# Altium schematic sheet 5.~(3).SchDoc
size 609 x 444 mm
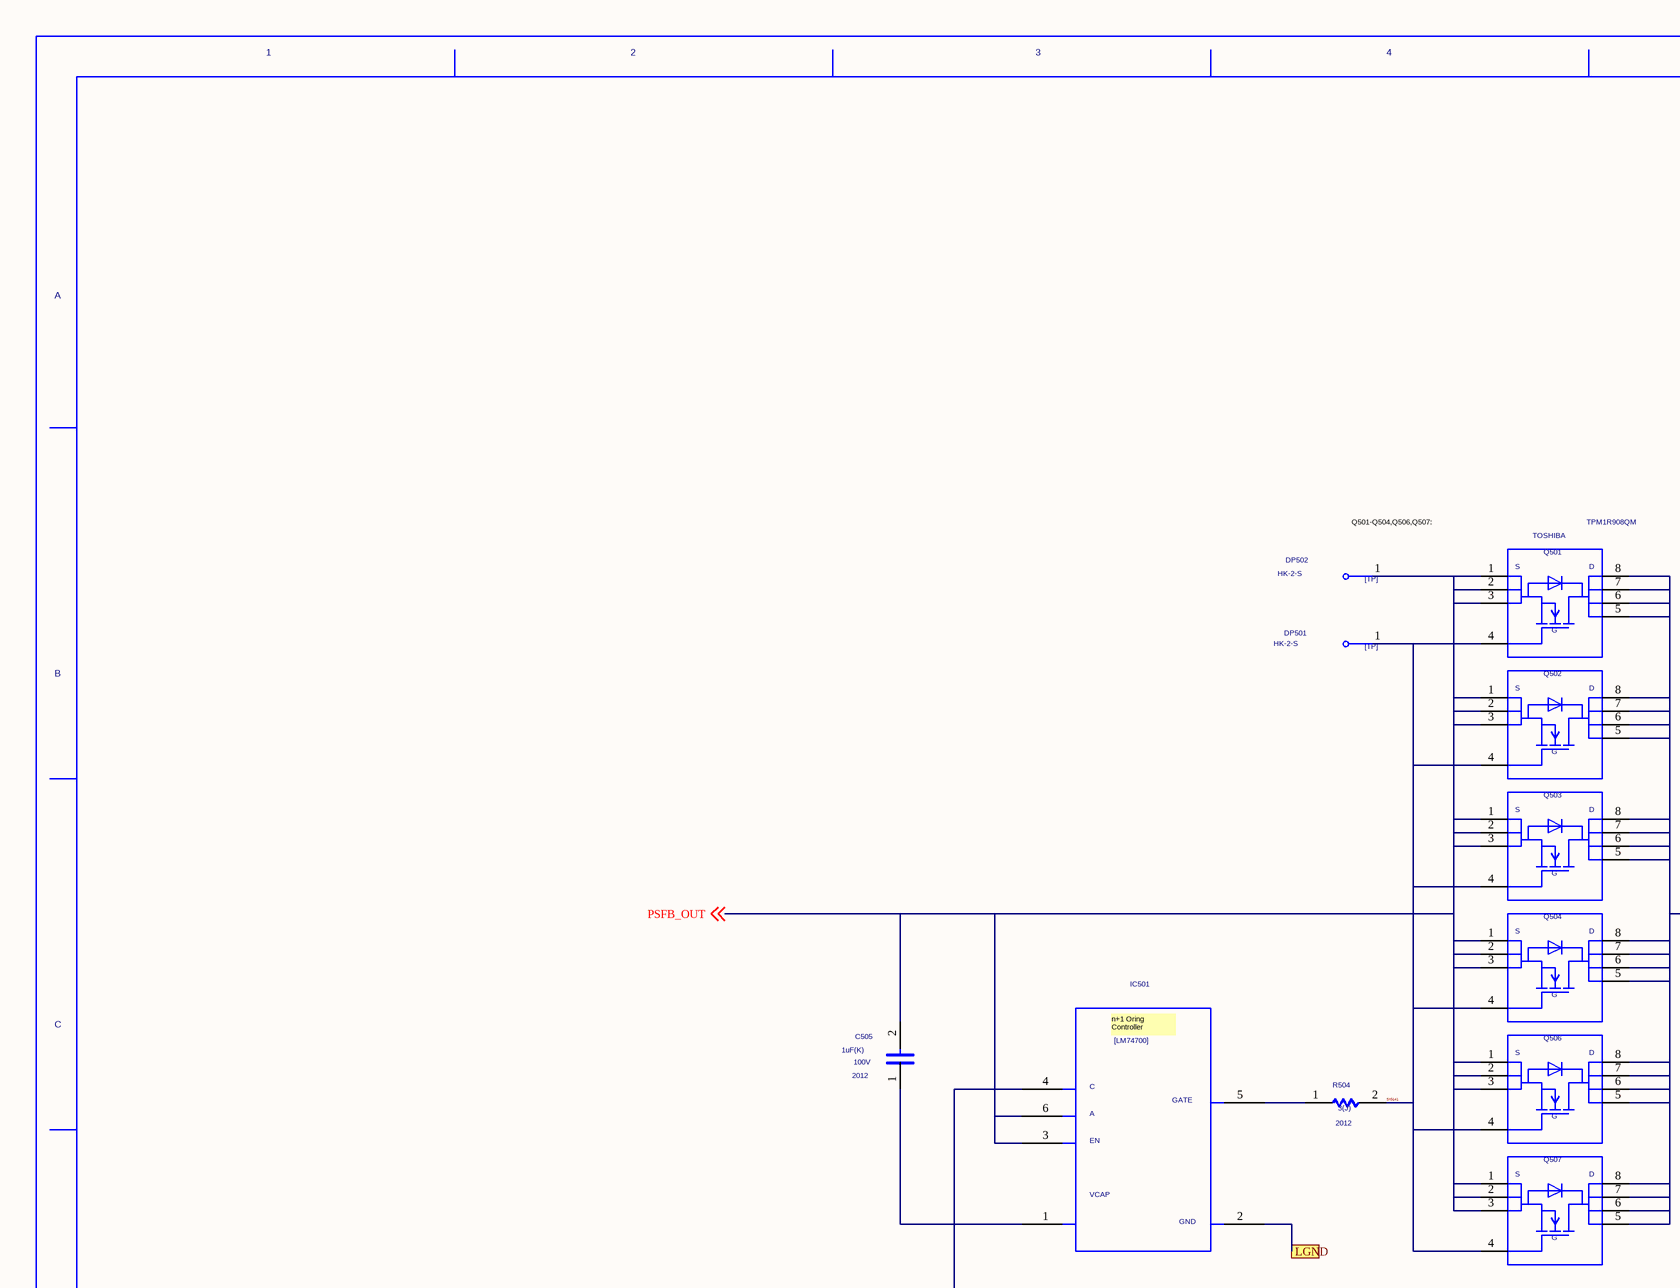
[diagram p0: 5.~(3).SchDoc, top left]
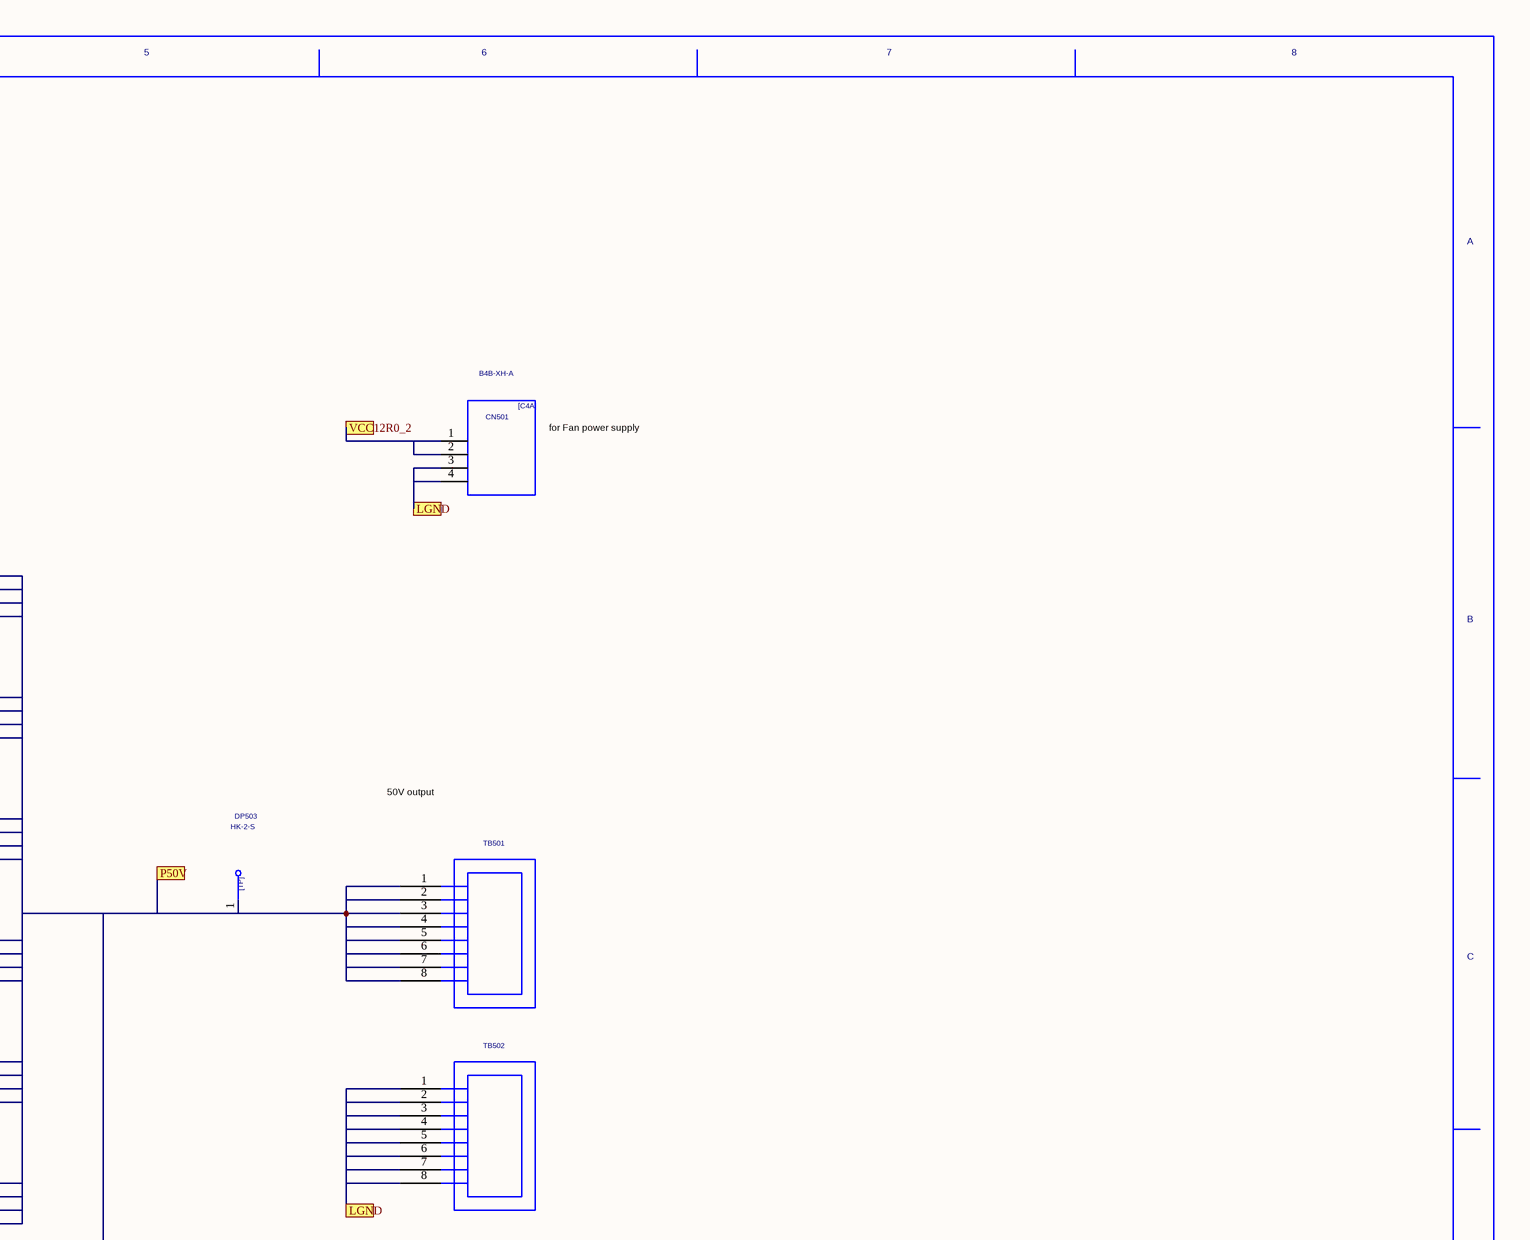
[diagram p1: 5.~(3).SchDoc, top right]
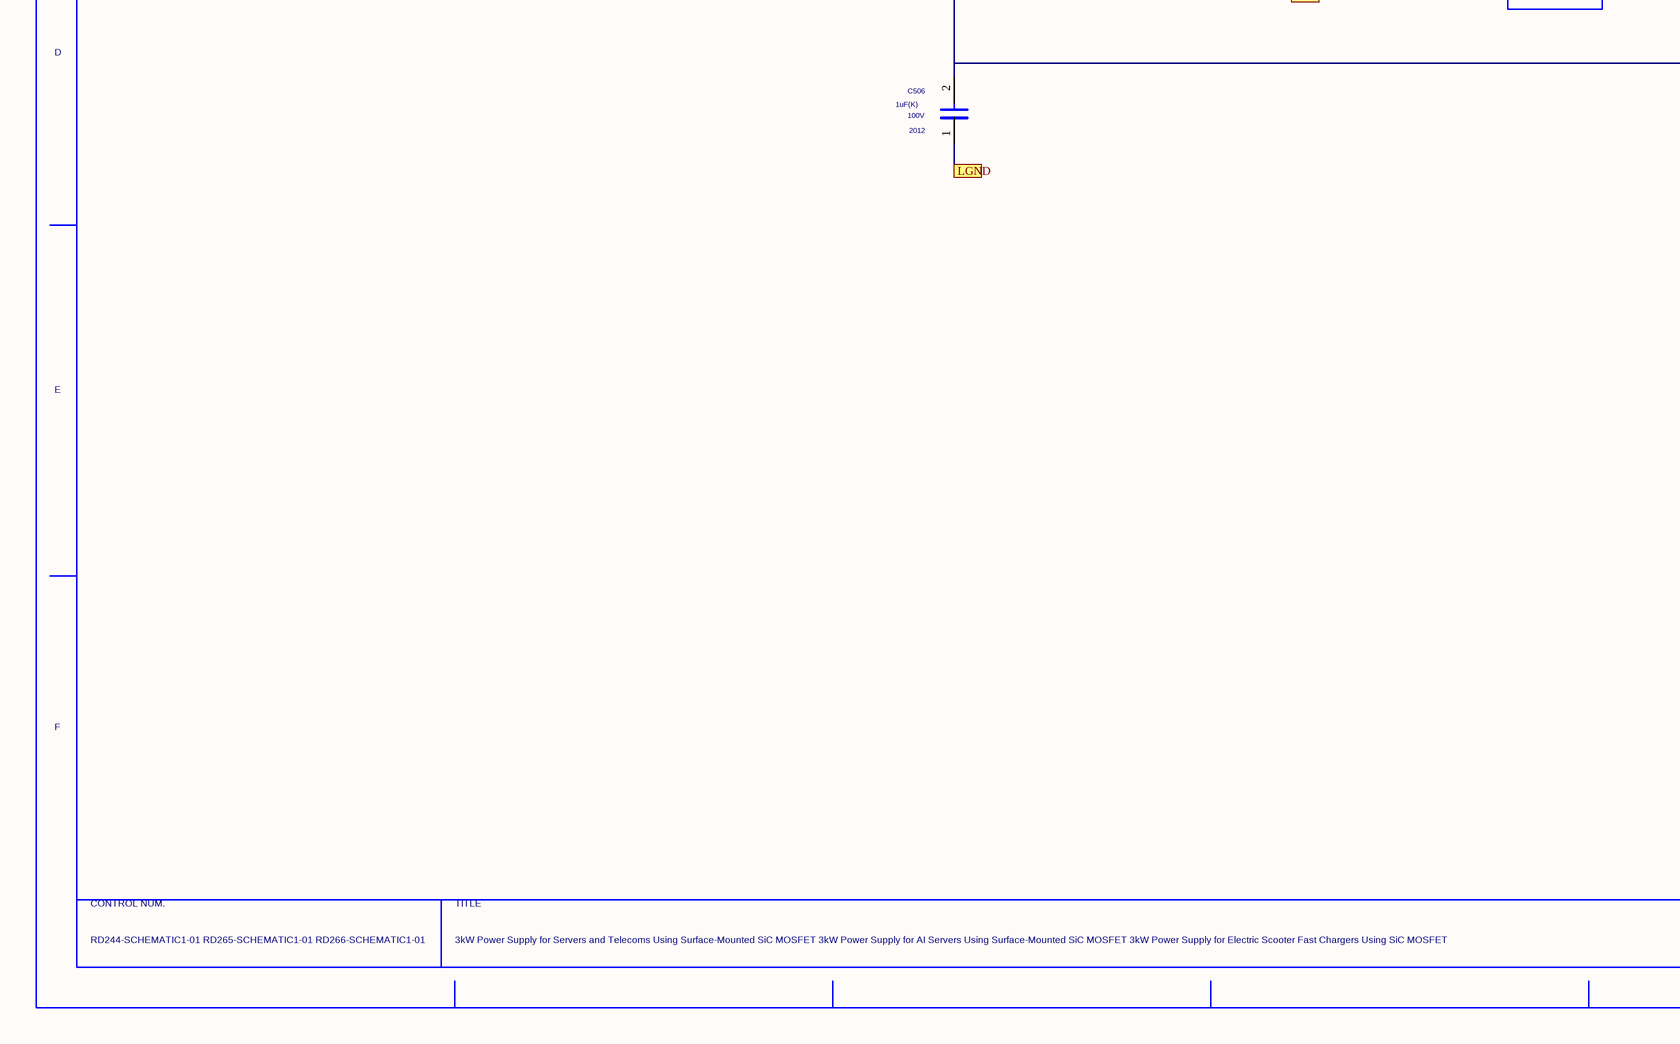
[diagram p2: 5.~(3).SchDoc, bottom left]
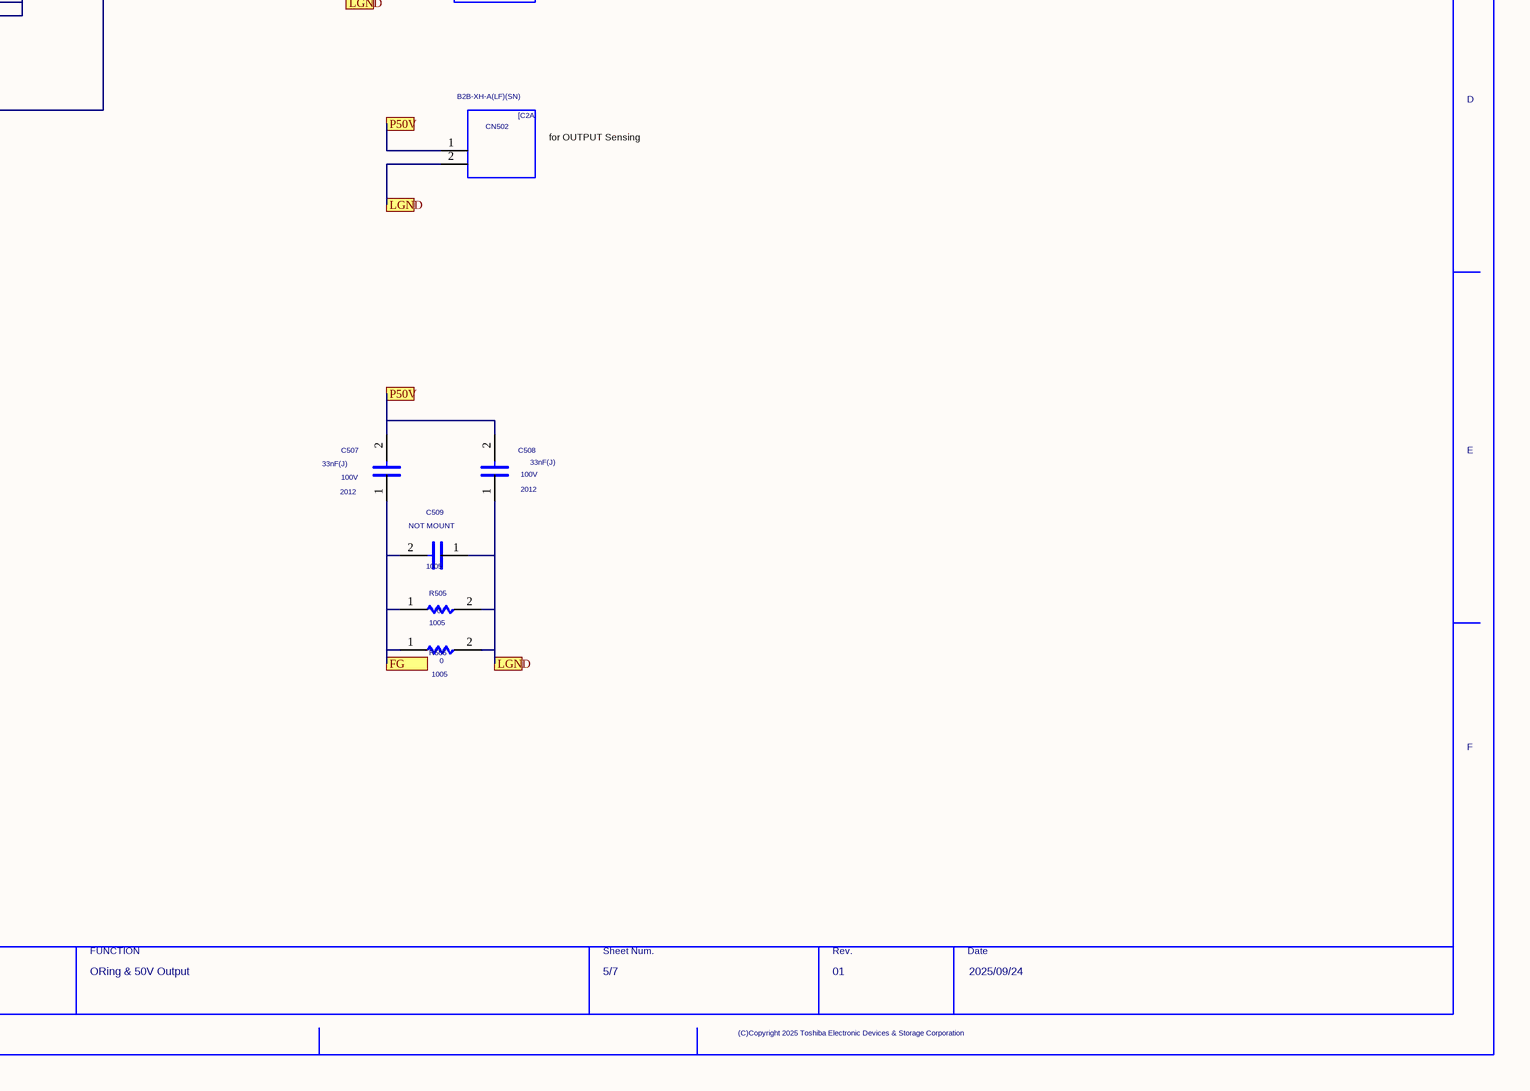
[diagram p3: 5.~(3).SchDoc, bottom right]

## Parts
C505  VAL1: 1uF(K)  VAL2: 100V  SIZECODESMD: 2012  (hidden comment: GRM21BC71E106KE01)
C506  VAL1: 1uF(K)  VAL2: 100V  SIZECODESMD: 2012  (hidden comment: GRM21BC71E106KE01)
C507  VAL1: 33nF(J)  VAL2: 100V  SIZECODESMD: 2012  (hidden comment: GRM21BC71E106KE01)
C508  VAL1: 33nF(J)  VAL2: 100V  SIZECODESMD: 2012  (hidden comment: GRM21BC71E106KE01)
C509  NOTMOUNT: NOT MOUNT  SIZECODESMD: 1005  (hidden comment: C)
CN501  VAL3: B4B-XH-A  (hidden comment: C4A)
CN502  VAL3: B2B-XH-A(LF)(SN)  (hidden comment: C2A)
DP501  VAL3: HK-2-S  (hidden comment: TP)
DP502  VAL3: HK-2-S  (hidden comment: TP)
DP503  VAL3: HK-2-S  (hidden comment: TP)
IC501  LM74700-Q1  (value not drawn)
Q501  VAL3: TPM1R908QM  USERCOMPTEXT3: TOSHIBA  (hidden comment: NCHMOSFET_SOPADVANCE-E-01)
Q502  NCHMOSFET_SOPADVANCE-E-01  (value not drawn)
Q503  NCHMOSFET_SOPADVANCE-E-01  (value not drawn)
Q504  NCHMOSFET_SOPADVANCE-E-01  (value not drawn)
Q506  NCHMOSFET_SOPADVANCE-E-01  (value not drawn)
Q507  NCHMOSFET_SOPADVANCE-E-01  (value not drawn)
R504  VAL1: 3(J)  SIZECODESMD: 2012  (hidden comment: R)
R505  VAL1: 0  SIZECODESMD: 1005  (hidden comment: R)
R506  VAL1: 0  SIZECODESMD: 1005  (hidden comment: R)
TB501  7460305  (value not drawn)
TB502  7460305  (value not drawn)
U?  DATE: 2025/09/24  DRAWINGNUMBER: RD244-SCHEMATIC1-01 / RD265-SCHEMATIC1-01 / RD266-SCHEMATIC1-01  TITLE: 3kW Power Supply for Servers and Telecoms Using Surface-Mounted SiC MOSFET / 3kW Power Supply for AI Servers Using Surface-Mounted SiC MOSFET / 3kW Power Supply for Electric Scooter Fast Chargers Using SiC MOSFET  FUNCTION: ORing & 50V Output  SHEETNUMBER: 5/7  REVISION: 01  (hidden comment: WAKU_DEF_A3_1)

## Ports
FG, LGND, P50V, VCC12R0_2

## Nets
FG: C507.1 C509.2 R505.1 R506.1 ; port FG
LGND: C506.1 C508.1 C509.1 CN501.3 CN501.4 CN502.2 IC501.2 R505.2 R506.2 TB502.1 TB502.2 TB502.3 TB502.4 TB502.5 TB502.6 TB502.7 TB502.8 ; port LGND
P50V: C506.2 C507.2 C508.2 CN502.1 DP503.1 IC501.4 Q501.5 Q501.6 Q501.7 Q501.8 Q502.5 Q502.6 Q502.7 Q502.8 Q503.5 Q503.6 Q503.7 Q503.8 Q504.5 Q504.6 Q504.7 Q504.8 Q506.5 Q506.6 Q506.7 Q506.8 Q507.5 Q507.6 Q507.7 Q507.8 TB501.1 TB501.2 TB501.3 TB501.4 TB501.5 TB501.6 TB501.7 TB501.8 ; port P50V
PSFB_OUT: C505.2 DP502.1 IC501.3 IC501.6 Q501.1 Q501.2 Q501.3 Q502.1 Q502.2 Q502.3 Q503.1 Q503.2 Q503.3 Q504.1 Q504.2 Q504.3 Q506.1 Q506.2 Q506.3 Q507.1 Q507.2 Q507.3 ; off-sheet PSFB_OUT
SIG122: C505.1 IC501.1
SIG136: IC501.5 R504.1
SIG141: DP501.1 Q501.4 Q502.4 Q503.4 Q504.4 Q506.4 Q507.4 R504.2
VCC12R0_2: CN501.1 CN501.2 ; port VCC12R0_2

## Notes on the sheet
- for Fan power supply
- (near DP502) Q501-Q504,Q506,Q507:
- 50V output
- for OUTPUT Sensing

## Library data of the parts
C505-C508 = GRM21BC71E106KE01: TIME: 10:25:11; UPDATEUSER: t4887876; UPDATETIME: 16:23:00; SAVECOUNT: 11; MAKER: Murata; OriginalSymbolOrigin: (2540,7620); CHIPSIZE: 1005; MAXGCOUNT: 1
C509 = C_Dup2: VAL1: 100nF(K); VAL2: 25V; OriginalSymbolOrigin: (2540,7620); COMP: PRT_52; MAXGCOUNT: 1; SAVECOUNT: 0
CN501 = C4A: SAVEAREA0: -8845,-265,28754,23475; SAVECOUNT: 22; TIME: 13:28:28; UPDATEUSER: tomizawa-y; UPDATETIME: 15:03:27; OriginalSymbolOrigin: (2540,20320); USERCOMPTEXT3: ローカライズ; COMPONENTNAME: K22S0019_package; MAXGCOUNT: 1; COMP: K22S0019; ADSCNVFLAG: ON
CN502 = C2A: OUMEPARTTYPE2: CN; SAVEAREA0: -4611,-206,24632,18258; SAVECOUNT: 25; TIME: 13:28:28; UPDATEUSER: tomizawa-y; UPDATETIME: 12:08:31; OriginalSymbolOrigin: (2540,15240); USERCOMPTEXT3: ローカライズ; COMPONENTNAME: K2203993_package; MAXGCOUNT: 1; COMP: K2203993; ADSCNVFLAG: ON
DP501-DP503 = TP: TIME: 16:12:21; UPDATEUSER: fukuda-y; UPDATETIME: 16:18:11; SAVECOUNT: 2; SAVEAREA0: -242,-92,12810,7836; OriginalSymbolOrigin: (0,7620); COMP: PRT_44
IC501 = LM74700-Q1: SAVEAREA0: -16399,-622,62276,51274; TIME: 11:49:52; UPDATEUSER: t4887876; UPDATETIME: 18:16:17; SAVECOUNT: 39; OriginalSymbolOrigin: (7620,48260)
Q501 = NCHMOSFET_SOPADVANCE-E-01: TIME: 18:29:30; UPDATEUSER: t4887876; UPDATETIME: 14:15:50; SAVECOUNT: 30; SAVEAREA0: -10143,-336,37609,28718; COMP: NchMOSFET_SOPAdvance(E)-01; VAL1: 80V; VAL2: **A; CHIPSET: ※型名を記入する; OriginalSymbolOrigin: (5080,22860); MAXGCOUNT: 1
Q502-Q504 Q506 Q507 = NCHMOSFET_SOPADVANCE-E-01: TIME: 18:29:30; UPDATEUSER: t4887876; UPDATETIME: 14:15:50; SAVECOUNT: 30; SAVEAREA0: -10143,-336,37609,28718; COMP: NchMOSFET_SOPAdvance(E)-01; VAL3: TPM1R908QM; VAL1: 80V; VAL2: **A; CHIPSET: ※型名を記入する; OriginalSymbolOrigin: (5080,22860); MAXGCOUNT: 1; USERCOMPTEXT3: TOSHIBA
R504 = R_Dup2: VAL2: 250mW; OriginalSymbolOrigin: (5080,5080); COMP: R2012; CHIPSIZE: 1608; MAXGCOUNT: 1; SAVECOUNT: 0
R505 R506 = R_Dup2: VAL2: 63mW; OriginalSymbolOrigin: (5080,5080); COMP: GDM010004481; CHIPSIZE: 1608; MAXGCOUNT: 1
TB501 TB502 = 7460305: SAVEAREA0: -4578,-286,40174,28213; SAVECOUNT: 17; TIME: 14:53:12; UPDATEUSER: t4887876; UPDATETIME: 16:00:29; VAL2: 160Amax; VAL1: M5; OriginalSymbolOrigin: (7620,27940); USERCOMPTEXT1: Wurth; MAXGCOUNT: 1; ADSCNVFLAG: ON
U? = WAKU_DEF_A3_1: PLOTTIME: HH:MM; SAVEAREA0: 96913,-567914,509243,-368858; TIME: 12:01:09; UPDATEUSER: t5459927; UPDATETIME: 13:12:48; SAVECOUNT: 3; ZONEOFFSETX: 36; ZONEOFFSETY: -24; OriginalSymbolOrigin: (12700,-12700); SHTSAVECOUNT: 121; PAGENUMBER: 5; DESIGNED: TOSHIBA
